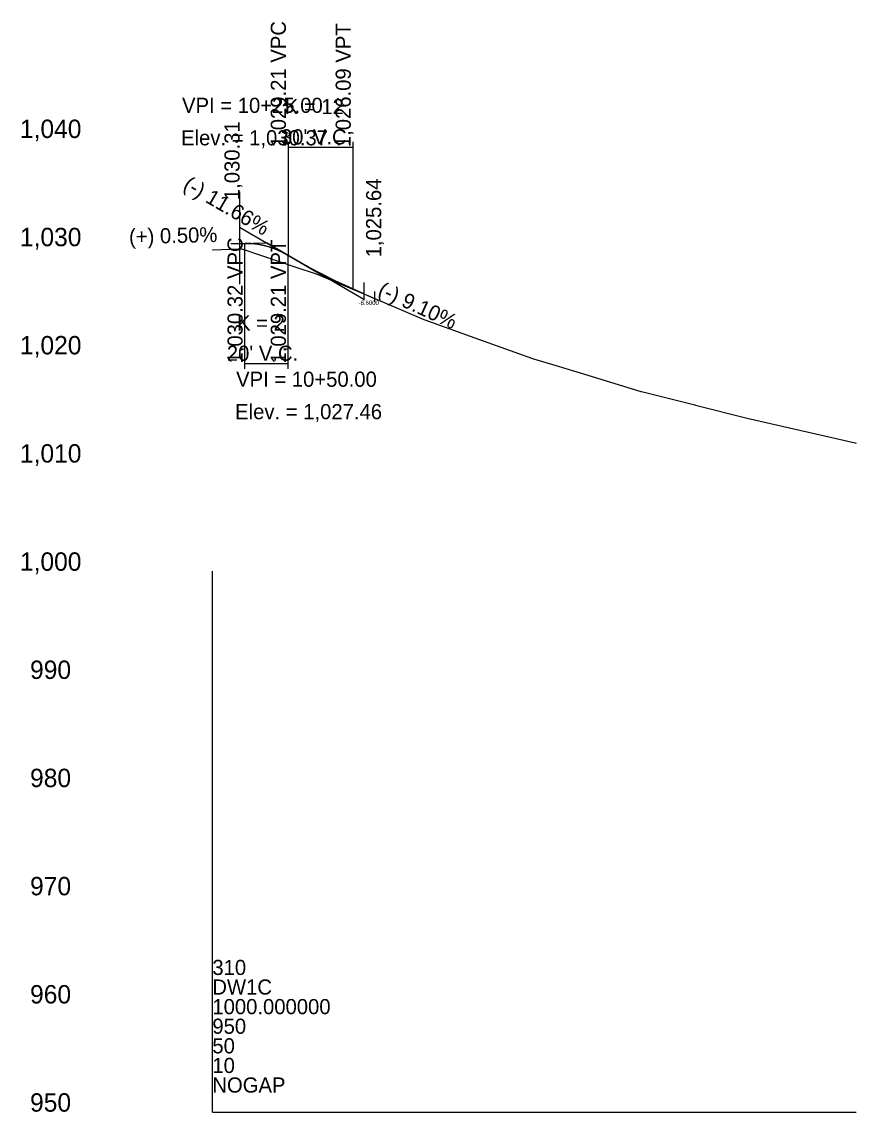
# Model space of a CAD drawing. Extents: x 1590191 to 1593577, y 1108634 to 1115609.
# Drawn here: x 1590191 to 1590577, y 1112643 to 1113147 of the extents above; entities that cross this region are included whole.
import ezdxf

# ---------------------------------------------------------------- set-up
doc = ezdxf.new("R2010")
doc.units = 0
for name, color, linetype in [('BR_USER NOTES', 7, 'Continuous'), ('RD_DDB_ElevTX', 7, 'Continuous'), ('RD_DDB_GradeTX', 7, 'Continuous'), ('RD_DDB_Profile_EX', 7, 'Continuous'), ('RD_DDB_Profile_Lbl', 7, 'Continuous'), ('RD_DDB_Profile_PR', 7, 'Continuous'), ('RD_DDB_StripGrade', 7, 'Continuous'), ('RD_DDB_VCLbl', 7, 'Continuous'), ('RD_GPK_Profile_Cell', 7, 'Continuous')]:
    doc.layers.add(name, color=color, linetype=linetype)

msp = doc.modelspace()

# ---------------------------------------------------------------- linework, layer by layer
at = {"layer": 'BR_USER NOTES'}
for p, q in [((1590291.6, 1113068.85), (1590291.6, 1113026.21)), ((1590287.51, 1113045.02), (1590296.66, 1113045.02)), ((1590349.01, 1113026.93), (1590349.01, 1113018.73)), ((1590354.01, 1113022.8), (1590354.01, 1113017.97)), ((1590349.01, 1113021.66), (1590354.01, 1113019.54))]:
    msp.add_line(p, q, dxfattribs=at)
at = {"layer": 'RD_DDB_GradeTX'}
for p, q in [((1590291.6, 1113052.57), (1590329.01, 1113030.76)), ((1590291.6, 1113045.02), (1590304.01, 1113045.33)), ((1590349.01, 1113019.1), (1590304.01, 1113045.33)), ((1590349.01, 1113021.66), (1590329.01, 1113030.76))]:
    msp.add_line(p, q, dxfattribs=at)
at = {"layer": 'RD_DDB_Profile_EX'}
msp.add_lwpolyline([(1590279.01, 1113042.05), (1590279.31, 1113042.1), (1590290.95, 1113042.45), (1590292.56, 1113042.49), (1590293.08, 1113042.35), (1590317.64, 1113034.1), (1590327.01, 1113030.96), (1590351.93, 1113020.43), (1590376.84, 1113009.89), (1590377.18, 1113009.74), (1590402.12, 1113000.81), (1590427.05, 1112991.87), (1590427.54, 1112991.71), (1590437.28, 1112988.75), (1590452.54, 1112984.09), (1590477.05, 1112976.62), (1590477.43, 1112976.52), (1590502.02, 1112970.35), (1590502.44, 1112970.24), (1590526.22, 1112964.28), (1590551.19, 1112958.54), (1590576.16, 1112952.81), (1590576.67, 1112952.7)], dxfattribs=at)
at = {"layer": 'RD_DDB_Profile_PR'}
for p, q in [((1590291.6, 1113045.02), (1590294.01, 1113045.08)), ((1590344.01, 1113023.93), (1590349.01, 1113021.66))]:
    msp.add_line(p, q, dxfattribs=at)
for points in [[(1590294.01, 1113045.08), (1590294.41, 1113045.09), (1590294.81, 1113045.1), (1590295.21, 1113045.09), (1590295.61, 1113045.09), (1590296.01, 1113045.07), (1590296.41, 1113045.06), (1590296.81, 1113045.04), (1590297.21, 1113045.01), (1590297.61, 1113044.98), (1590298.01, 1113044.94), (1590298.41, 1113044.9), (1590298.81, 1113044.85), (1590299.21, 1113044.8), (1590299.61, 1113044.75), (1590300.01, 1113044.69), (1590300.41, 1113044.62), (1590300.81, 1113044.55), (1590301.21, 1113044.48), (1590301.61, 1113044.4), (1590302.01, 1113044.31), (1590302.41, 1113044.22), (1590302.81, 1113044.13), (1590303.21, 1113044.03), (1590303.61, 1113043.92), (1590304.01, 1113043.81), (1590304.41, 1113043.7), (1590304.81, 1113043.58), (1590305.21, 1113043.46), (1590305.61, 1113043.33), (1590306.01, 1113043.2), (1590306.41, 1113043.06), (1590306.81, 1113042.91), (1590307.21, 1113042.77), (1590307.61, 1113042.61), (1590308.01, 1113042.46), (1590308.41, 1113042.29), (1590308.81, 1113042.13), (1590309.21, 1113041.95), (1590309.61, 1113041.78), (1590310.01, 1113041.59), (1590310.41, 1113041.41), (1590310.81, 1113041.21), (1590311.21, 1113041.02), (1590311.61, 1113040.82), (1590312.01, 1113040.61), (1590312.41, 1113040.4), (1590312.81, 1113040.18), (1590313.21, 1113039.96), (1590313.61, 1113039.74), (1590314.01, 1113039.5)], [(1590314.01, 1113039.5), (1590314.61, 1113039.16), (1590315.21, 1113038.81), (1590315.81, 1113038.46), (1590316.41, 1113038.12), (1590317.01, 1113037.78), (1590317.61, 1113037.43), (1590318.21, 1113037.09), (1590318.81, 1113036.76), (1590319.41, 1113036.42), (1590320.01, 1113036.08), (1590320.61, 1113035.75), (1590321.21, 1113035.42), (1590321.81, 1113035.09), (1590322.41, 1113034.76), (1590323.01, 1113034.43), (1590323.61, 1113034.1), (1590324.21, 1113033.78), (1590324.81, 1113033.46), (1590325.41, 1113033.14), (1590326.01, 1113032.82), (1590326.61, 1113032.5), (1590327.21, 1113032.18), (1590327.81, 1113031.87), (1590328.41, 1113031.55), (1590329.01, 1113031.24), (1590329.61, 1113030.93), (1590330.21, 1113030.62), (1590330.81, 1113030.31), (1590331.41, 1113030.01), (1590332.01, 1113029.7), (1590332.61, 1113029.4), (1590333.21, 1113029.1), (1590333.81, 1113028.8), (1590334.41, 1113028.5), (1590335.01, 1113028.2), (1590335.61, 1113027.91), (1590336.21, 1113027.61), (1590336.81, 1113027.32), (1590337.41, 1113027.03), (1590338.01, 1113026.74), (1590338.61, 1113026.45), (1590339.21, 1113026.17), (1590339.81, 1113025.88), (1590340.41, 1113025.6), (1590341.01, 1113025.32), (1590341.61, 1113025.04), (1590342.21, 1113024.76), (1590342.81, 1113024.48), (1590343.41, 1113024.21), (1590344.01, 1113023.93)]]:
    msp.add_spline(points, degree=3, dxfattribs=at)
at = {"layer": 'RD_DDB_VCLbl'}
for p, q in [((1590314.01, 1113092), (1590314.01, 1113039.5)), ((1590314.01, 1113089.5), (1590344.01, 1113089.5)), ((1590344.01, 1113092), (1590344.01, 1113023.93)), ((1590294.01, 1112987), (1590294.01, 1113045.08)), ((1590314.01, 1112987), (1590314.01, 1113039.5)), ((1590294.01, 1112989.5), (1590314.01, 1112989.5))]:
    msp.add_line(p, q, dxfattribs=at)
at = {"layer": 'RD_GPK_Profile_Cell'}
for q in [(1590279.01, 1112893.47), (1590576.67, 1112643.47), (1590279.01, 1112643.47)]:
    msp.add_line((1590279.01, 1112643.47), q, dxfattribs=at)

# ---------------------------------------------------------------- texts
at = {"layer": 'BR_USER NOTES'}
msp.add_text('-8.6000', height=2, dxfattribs=at).set_placement((1590346.6, 1113016.61))
at = {"layer": 'RD_DDB_ElevTX'}
for s, p in [('1,040', (1590190.05, 1113093.72)), ('1,030', (1590190.05, 1113043.72)), ('1,020', (1590190.05, 1112993.72)), ('1,010', (1590190.05, 1112943.72)), ('1,000', (1590190.05, 1112893.72)), ('990', (1590194.73, 1112843.72)), ('980', (1590194.73, 1112793.72)), ('970', (1590194.73, 1112743.72)), ('960', (1590194.73, 1112693.72)), ('950', (1590194.73, 1112643.72))]:
    msp.add_text(s, height=8.5, dxfattribs=at).set_placement(p)
at = {"layer": 'RD_DDB_GradeTX'}
for s, rotation, p in [('(-) 11.66%', 329.7575, (1590265, 1113070.39)), ('(+) 0.50%', 1.4321, (1590240.56, 1113044.64)), ('(-) 9.10%', 335.5345, (1590355.04, 1113021.12))]:
    msp.add_text(s, height=7, rotation=rotation, dxfattribs=at).set_placement(p)
at = {"layer": 'RD_DDB_Profile_Lbl'}
for s, p in [('VPI = 10+25.00', (1590264.99, 1113105.33)), ('Elev. = 1,030.37', (1590264.55, 1113090.33)), ('VPI = 10+50.00', (1590289.99, 1112978.76)), ('Elev. = 1,027.46', (1590289.55, 1112963.76))]:
    msp.add_text(s, height=7, dxfattribs=at).set_placement(p)
for s, p in [('1,030.31', (1590291.6, 1113065.02)), ('1,025.64', (1590357.06, 1113038.57))]:
    msp.add_text(s, height=7, rotation=90, dxfattribs=at).set_placement(p)
at = {"layer": 'RD_DDB_StripGrade'}
for s, p in [('1,029.21 VPC', (1590313.01, 1113089.5)), ('1,026.09 VPT', (1590343.01, 1113089.5)), ('1,030.32 VPC', (1590293.01, 1112989.5)), ('1,029.21 VPT', (1590313.01, 1112989.5))]:
    msp.add_text(s, height=7, rotation=90, dxfattribs=at).set_placement(p)
at = {"layer": 'RD_DDB_VCLbl'}
for s, p in [('K = 12', (1590312.47, 1113104.75)), ("30' V.C.", (1590310.7, 1113090.75)), ('K = 2', (1590290.41, 1113004.75)), ("20' V.C.", (1590285.7, 1112990.75))]:
    msp.add_text(s, height=7, dxfattribs=at).set_placement(p)
at = {"layer": 'RD_GPK_Profile_Cell'}
for s, p in [('310', (1590279.01, 1112706.89)), ('DW1C', (1590279.01, 1112697.83)), ('1000.000000', (1590279.01, 1112688.77)), ('950', (1590279.01, 1112679.71)), ('50', (1590279.01, 1112670.65)), ('10', (1590279.01, 1112661.59)), ('NOGAP', (1590279.01, 1112652.53))]:
    msp.add_text(s, height=7, dxfattribs=at).set_placement(p)

doc.saveas('drawing.dxf')
